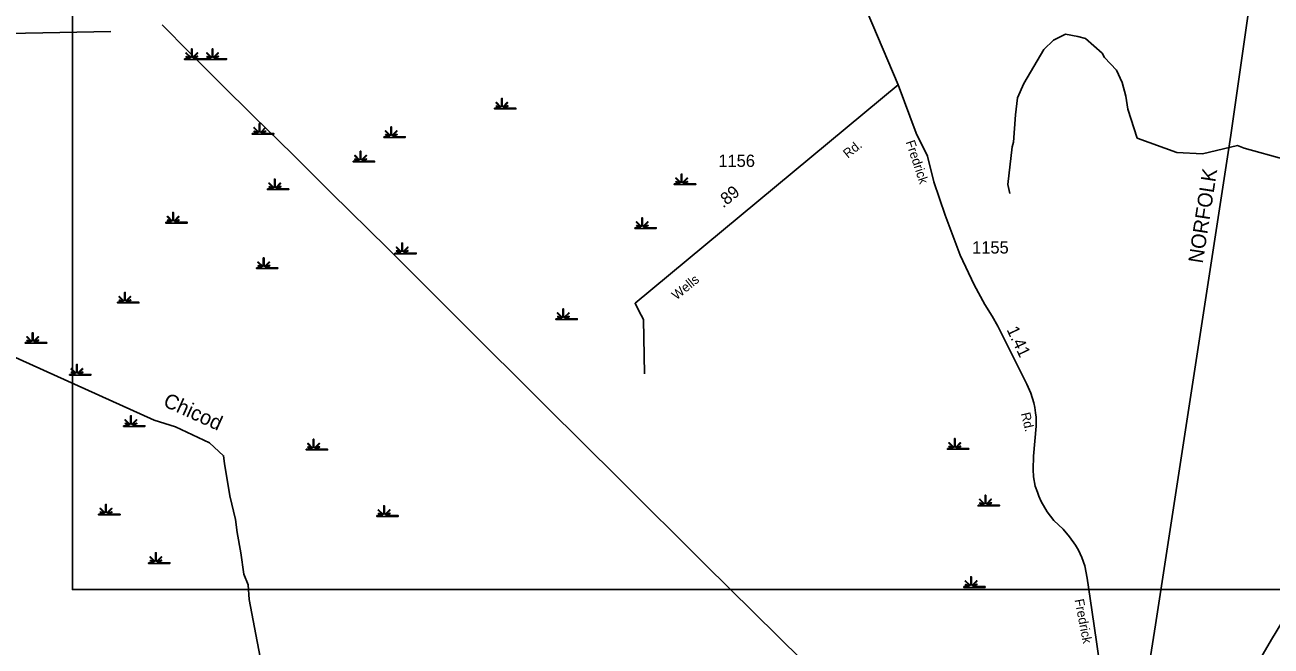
# Model space of a CAD drawing. Extents: x 2532689 to 2764727, y 536648 to 732970.
# Drawn here: x 2549089 to 2561755, y 635778 to 642091 of the extents above; entities that cross this region are included whole.
import ezdxf

# ---------------------------------------------------------------- set-up
doc = ezdxf.new("R2010")
doc.units = 0
for name, color, linetype in [('Exist Hydrographic Creek Single Shore', 7, 'Continuous'), ('Exist Hydrographic Creek Single Shore Label', 7, 'Continuous'), ('Exist Hydrographic Swamp CELL', 7, 'Continuous'), ('Exist Railroad Mainline', 7, 'Continuous'), ('Exist Railroad Mainline Label', 7, 'Continuous'), ('Exist Road Primary US Divided Attributed', 7, 'Continuous'), ('Exist Road Secondary Mileage Hundredths English Label', 7, 'Continuous'), ('Exist Road Secondary Type 20 Attributed', 7, 'Continuous'), ('Exist Road Secondary Type 51 Attributed', 7, 'Continuous'), ('Exist Road Secondary Type 51 Label', 7, 'Continuous'), ('Exist Road Secondary Type 51 Number Label', 7, 'Continuous'), ('Exist Utilities Electrical Transmission Line', 7, 'Continuous'), ('Map Preparation Inset Cut Line', 7, 'Continuous'), ('Map Preparation Longitude Latitude Lines', 7, 'Continuous')]:
    doc.layers.add(name, color=color, linetype=linetype)

msp = doc.modelspace()

# ---------------------------------------------------------------- linework, layer by layer
at = {"layer": 'Exist Hydrographic Creek Single Shore'}
for points in [[(2559098, 640377), (2559079, 640469), (2559122, 640851), (2559137, 640901), (2559157, 641178), (2559179, 641352), (2559242, 641496), (2559444, 641843), (2559542, 641935), (2559666, 641996), (2559791, 641975), (2559867, 641952), (2560037, 641804), (2560062, 641762), (2560182, 641633), (2560242, 641507), (2560278, 641367), (2560298, 641234), (2560395, 640942), (2560798, 640794), (2561056, 640782), (2561413, 640865), (2561481, 640838), (2561899, 640724)], [(2551589, 635080), (2551544, 635256), (2551534, 635380), (2551368, 636250), (2551357, 636400), (2551313, 636510), (2551284, 636726), (2551247, 636931), (2551228, 637065), (2551173, 637306), (2551118, 637632), (2551108, 637713), (2550964, 637845), (2550619, 638005), (2550401, 638075), (2548712, 638838)]]:
    msp.add_lwpolyline(points, dxfattribs=at)
at = {"layer": 'Exist Hydrographic Swamp CELL'}
for points in [[(2550710, 641748), (2550763, 641748), (2550765, 641751), (2550726, 641766), (2550729, 641772), (2550767, 641756), (2550769, 641759), (2550724, 641803), (2550729, 641808), (2550775, 641763), (2550781, 641765), (2550781, 641848), (2550788, 641848), (2550788, 641765), (2550795, 641763), (2550840, 641808), (2550845, 641803), (2550801, 641759), (2550803, 641755), (2550843, 641774), (2550846, 641769), (2550805, 641751), (2550807, 641748), (2550928, 641748), (2550928, 641741), (2550710, 641741)], [(2550921, 641748), (2550974, 641748), (2550976, 641751), (2550937, 641766), (2550940, 641772), (2550978, 641756), (2550980, 641759), (2550935, 641803), (2550940, 641808), (2550986, 641763), (2550992, 641765), (2550992, 641848), (2550999, 641848), (2550999, 641765), (2551006, 641763), (2551051, 641808), (2551056, 641803), (2551012, 641759), (2551014, 641755), (2551054, 641774), (2551057, 641769), (2551016, 641751), (2551018, 641748), (2551139, 641748), (2551139, 641741), (2550921, 641741)], [(2553862, 641245), (2553915, 641245), (2553917, 641248), (2553879, 641263), (2553881, 641268), (2553919, 641253), (2553921, 641256), (2553876, 641300), (2553881, 641305), (2553927, 641260), (2553933, 641262), (2553933, 641345), (2553940, 641345), (2553940, 641262), (2553947, 641260), (2553992, 641305), (2553997, 641300), (2553953, 641256), (2553955, 641252), (2553996, 641271), (2553998, 641265), (2553957, 641248), (2553959, 641245), (2554080, 641245), (2554080, 641238), (2553862, 641238)], [(2551400, 640988), (2551453, 640988), (2551455, 640992), (2551417, 641007), (2551420, 641012), (2551457, 640996), (2551459, 640999), (2551414, 641044), (2551420, 641049), (2551465, 641003), (2551471, 641006), (2551471, 641089), (2551478, 641089), (2551478, 641006), (2551485, 641003), (2551530, 641049), (2551535, 641044), (2551491, 640999), (2551493, 640996), (2551534, 641014), (2551536, 641009), (2551495, 640991), (2551497, 640988), (2551618, 640988), (2551618, 640981), (2551400, 640981)], [(2552737, 640955), (2552790, 640955), (2552792, 640959), (2552753, 640973), (2552756, 640979), (2552794, 640963), (2552796, 640966), (2552751, 641010), (2552756, 641015), (2552802, 640970), (2552808, 640972), (2552808, 641055), (2552815, 641055), (2552815, 640972), (2552822, 640970), (2552867, 641015), (2552872, 641010), (2552828, 640966), (2552830, 640962), (2552870, 640981), (2552873, 640976), (2552832, 640958), (2552834, 640955), (2552955, 640955), (2552955, 640948), (2552737, 640948)], [(2552426, 640706), (2552479, 640706), (2552481, 640710), (2552442, 640725), (2552445, 640730), (2552483, 640714), (2552485, 640717), (2552440, 640762), (2552445, 640767), (2552491, 640721), (2552497, 640724), (2552497, 640807), (2552504, 640807), (2552504, 640724), (2552510, 640721), (2552556, 640767), (2552561, 640762), (2552516, 640717), (2552518, 640714), (2552559, 640732), (2552562, 640727), (2552521, 640709), (2552522, 640706), (2552643, 640706), (2552643, 640699), (2552426, 640699)], [(2551554, 640425), (2551607, 640425), (2551609, 640429), (2551570, 640443), (2551573, 640449), (2551611, 640433), (2551613, 640436), (2551568, 640480), (2551573, 640485), (2551619, 640440), (2551625, 640442), (2551625, 640525), (2551632, 640525), (2551632, 640442), (2551638, 640440), (2551684, 640485), (2551689, 640480), (2551644, 640436), (2551646, 640432), (2551687, 640451), (2551690, 640446), (2551649, 640428), (2551650, 640425), (2551771, 640425), (2551771, 640418), (2551554, 640418)], [(2555689, 640476), (2555742, 640476), (2555744, 640479), (2555705, 640494), (2555708, 640499), (2555746, 640484), (2555748, 640486), (2555703, 640531), (2555708, 640536), (2555754, 640491), (2555760, 640493), (2555760, 640576), (2555767, 640576), (2555767, 640493), (2555774, 640491), (2555819, 640536), (2555824, 640531), (2555780, 640486), (2555782, 640483), (2555822, 640501), (2555825, 640496), (2555784, 640479), (2555786, 640476), (2555907, 640476), (2555907, 640468), (2555689, 640468)], [(2550520, 640085), (2550573, 640086), (2550575, 640089), (2550537, 640104), (2550540, 640109), (2550577, 640093), (2550579, 640096), (2550534, 640141), (2550540, 640146), (2550585, 640100), (2550591, 640103), (2550591, 640186), (2550598, 640186), (2550598, 640103), (2550605, 640100), (2550650, 640146), (2550655, 640141), (2550611, 640096), (2550613, 640093), (2550654, 640111), (2550656, 640106), (2550615, 640088), (2550617, 640086), (2550738, 640085), (2550738, 640078), (2550520, 640078)], [(2555288, 640030), (2555341, 640030), (2555343, 640033), (2555304, 640048), (2555307, 640053), (2555345, 640038), (2555347, 640041), (2555302, 640085), (2555307, 640090), (2555353, 640045), (2555359, 640047), (2555359, 640130), (2555366, 640130), (2555366, 640047), (2555372, 640045), (2555418, 640090), (2555423, 640085), (2555379, 640041), (2555381, 640037), (2555421, 640056), (2555424, 640051), (2555383, 640033), (2555384, 640030), (2555506, 640030), (2555506, 640023), (2555288, 640023)], [(2552848, 639773), (2552901, 639773), (2552903, 639777), (2552865, 639792), (2552868, 639797), (2552905, 639781), (2552907, 639784), (2552863, 639829), (2552868, 639834), (2552913, 639788), (2552919, 639791), (2552919, 639874), (2552927, 639874), (2552927, 639791), (2552933, 639788), (2552978, 639834), (2552983, 639829), (2552939, 639784), (2552941, 639781), (2552982, 639799), (2552984, 639794), (2552943, 639776), (2552945, 639773), (2553066, 639773), (2553066, 639766), (2552848, 639766)], [(2551441, 639623), (2551494, 639623), (2551496, 639626), (2551458, 639641), (2551461, 639646), (2551498, 639631), (2551500, 639634), (2551456, 639678), (2551461, 639683), (2551506, 639638), (2551512, 639640), (2551512, 639723), (2551520, 639723), (2551520, 639640), (2551526, 639638), (2551571, 639683), (2551576, 639678), (2551532, 639634), (2551534, 639630), (2551575, 639649), (2551577, 639644), (2551536, 639626), (2551538, 639623), (2551659, 639623), (2551659, 639616), (2551441, 639616)], [(2550030, 639272), (2550083, 639272), (2550085, 639275), (2550046, 639290), (2550049, 639295), (2550087, 639280), (2550089, 639283), (2550044, 639327), (2550049, 639332), (2550095, 639287), (2550101, 639289), (2550101, 639372), (2550108, 639372), (2550108, 639289), (2550115, 639287), (2550160, 639332), (2550165, 639327), (2550121, 639283), (2550123, 639279), (2550163, 639298), (2550166, 639293), (2550125, 639275), (2550127, 639272), (2550248, 639272), (2550248, 639265), (2550030, 639265)], [(2554486, 639105), (2554539, 639105), (2554541, 639108), (2554502, 639123), (2554505, 639128), (2554543, 639112), (2554545, 639115), (2554500, 639160), (2554505, 639165), (2554551, 639120), (2554557, 639122), (2554557, 639205), (2554564, 639205), (2554564, 639122), (2554570, 639120), (2554616, 639165), (2554621, 639160), (2554576, 639115), (2554578, 639112), (2554619, 639130), (2554622, 639125), (2554581, 639108), (2554582, 639105), (2554703, 639105), (2554703, 639097), (2554486, 639097)], [(2549093, 638863), (2549145, 638863), (2549147, 638866), (2549109, 638881), (2549112, 638886), (2549150, 638871), (2549151, 638874), (2549107, 638918), (2549112, 638923), (2549157, 638878), (2549164, 638880), (2549164, 638963), (2549171, 638963), (2549171, 638880), (2549177, 638878), (2549222, 638923), (2549228, 638918), (2549183, 638874), (2549185, 638870), (2549226, 638889), (2549228, 638884), (2549187, 638866), (2549189, 638863), (2549310, 638863), (2549310, 638856), (2549093, 638856)], [(2549543, 638539), (2549595, 638539), (2549597, 638543), (2549559, 638558), (2549562, 638563), (2549600, 638547), (2549601, 638550), (2549557, 638594), (2549562, 638600), (2549607, 638554), (2549614, 638556), (2549614, 638640), (2549621, 638640), (2549621, 638556), (2549627, 638554), (2549672, 638600), (2549678, 638594), (2549633, 638550), (2549635, 638546), (2549676, 638565), (2549679, 638560), (2549638, 638542), (2549639, 638539), (2549760, 638539), (2549760, 638532), (2549543, 638532)], [(2550091, 638018), (2550144, 638018), (2550146, 638022), (2550108, 638037), (2550111, 638042), (2550148, 638026), (2550150, 638029), (2550105, 638074), (2550111, 638079), (2550156, 638033), (2550162, 638036), (2550162, 638119), (2550169, 638119), (2550169, 638036), (2550176, 638033), (2550221, 638079), (2550226, 638074), (2550182, 638029), (2550184, 638026), (2550225, 638044), (2550227, 638039), (2550186, 638021), (2550188, 638018), (2550309, 638018), (2550309, 638011), (2550091, 638011)], [(2551948, 637779), (2552000, 637779), (2552002, 637783), (2551964, 637798), (2551967, 637803), (2552005, 637787), (2552006, 637790), (2551962, 637834), (2551967, 637840), (2552012, 637794), (2552019, 637797), (2552019, 637880), (2552026, 637880), (2552026, 637797), (2552032, 637794), (2552078, 637840), (2552083, 637834), (2552038, 637790), (2552040, 637786), (2552081, 637805), (2552084, 637800), (2552043, 637782), (2552044, 637779), (2552165, 637779), (2552165, 637772), (2551948, 637772)], [(2558465, 637785), (2558518, 637785), (2558520, 637789), (2558481, 637804), (2558484, 637809), (2558522, 637793), (2558524, 637796), (2558479, 637841), (2558484, 637846), (2558530, 637800), (2558536, 637803), (2558536, 637886), (2558543, 637886), (2558543, 637803), (2558549, 637800), (2558595, 637846), (2558600, 637841), (2558555, 637796), (2558557, 637793), (2558598, 637811), (2558601, 637806), (2558560, 637788), (2558561, 637785), (2558682, 637785), (2558682, 637778), (2558465, 637778)], [(2549838, 637118), (2549891, 637118), (2549893, 637121), (2549854, 637136), (2549857, 637141), (2549895, 637126), (2549897, 637128), (2549852, 637173), (2549857, 637178), (2549903, 637133), (2549909, 637135), (2549909, 637218), (2549916, 637218), (2549916, 637135), (2549923, 637133), (2549968, 637178), (2549973, 637173), (2549929, 637128), (2549931, 637125), (2549971, 637143), (2549974, 637138), (2549933, 637121), (2549935, 637118), (2550056, 637118), (2550056, 637111), (2549838, 637111)], [(2558777, 637210), (2558829, 637210), (2558831, 637214), (2558793, 637229), (2558796, 637234), (2558834, 637218), (2558835, 637221), (2558791, 637266), (2558796, 637271), (2558841, 637225), (2558848, 637228), (2558848, 637311), (2558855, 637311), (2558855, 637228), (2558861, 637225), (2558907, 637271), (2558912, 637266), (2558867, 637221), (2558869, 637217), (2558910, 637236), (2558913, 637231), (2558872, 637213), (2558873, 637210), (2558994, 637210), (2558994, 637203), (2558777, 637203)], [(2552665, 637104), (2552718, 637104), (2552720, 637107), (2552681, 637122), (2552684, 637127), (2552722, 637112), (2552724, 637114), (2552679, 637159), (2552684, 637164), (2552730, 637119), (2552736, 637121), (2552736, 637204), (2552743, 637204), (2552743, 637121), (2552750, 637119), (2552795, 637164), (2552800, 637159), (2552756, 637114), (2552758, 637111), (2552798, 637129), (2552801, 637124), (2552760, 637107), (2552762, 637104), (2552883, 637104), (2552883, 637096), (2552665, 637096)], [(2550344, 636625), (2550397, 636625), (2550399, 636629), (2550361, 636644), (2550364, 636649), (2550401, 636633), (2550403, 636636), (2550359, 636680), (2550364, 636686), (2550409, 636640), (2550415, 636642), (2550415, 636726), (2550423, 636726), (2550423, 636642), (2550429, 636640), (2550474, 636686), (2550479, 636680), (2550435, 636636), (2550437, 636632), (2550478, 636651), (2550480, 636646), (2550439, 636628), (2550441, 636625), (2550562, 636625), (2550562, 636618), (2550344, 636618)], [(2558631, 636382), (2558683, 636382), (2558685, 636385), (2558647, 636400), (2558650, 636405), (2558688, 636390), (2558689, 636392), (2558645, 636437), (2558650, 636442), (2558695, 636397), (2558702, 636399), (2558702, 636482), (2558709, 636482), (2558709, 636399), (2558715, 636397), (2558760, 636442), (2558766, 636437), (2558721, 636392), (2558723, 636389), (2558764, 636407), (2558766, 636402), (2558725, 636385), (2558727, 636382), (2558848, 636382), (2558848, 636374), (2558631, 636374)]]:
    msp.add_lwpolyline(points, close=True, dxfattribs=at)
at = {"layer": 'Exist Railroad Mainline'}
msp.add_lwpolyline([(2559836, 631017), (2560198, 633565), (2560580, 635992), (2561345, 640971), (2561535, 642299), (2561640, 643031)], dxfattribs=at)
at = {"layer": 'Exist Road Primary US Divided Attributed'}
msp.add_lwpolyline([(2560987, 634551), (2561007, 634587), (2561581, 635545), (2561649, 635658), (2561760, 635844), (2561864, 636016), (2561980, 636211), (2562085, 636388), (2562163, 636518), (2562307, 636758), (2562445, 636986), (2562519, 637112), (2562643, 637320), (2562996, 637912), (2563069, 638047), (2563124, 638171), (2563159, 638272), (2563197, 638390)], dxfattribs=at)
at = {"layer": 'Exist Road Secondary Type 20 Attributed'}
msp.add_lwpolyline([(2557966, 641483), (2555291, 639262), (2555330, 639185), (2555377, 639096), (2555385, 638545)], dxfattribs=at)
at = {"layer": 'Exist Road Secondary Type 51 Attributed'}
for points in [[(2557966, 641483), (2557648, 642225), (2557577, 642400), (2557487, 642620), (2557407, 642842), (2557384, 642904), (2557366, 642976), (2557344, 643077), (2557318, 643209), (2557279, 643460), (2557236, 643759), (2557193, 644009), (2557175, 644120), (2557162, 644212)], [(2560043, 635375), (2559983, 635798), (2559933, 636147), (2559887, 636469), (2559860, 636595), (2559831, 636679), (2559798, 636753), (2559767, 636803), (2559707, 636887), (2559640, 636965), (2559545, 637055), (2559478, 637142), (2559419, 637248), (2559393, 637300), (2559379, 637341), (2559357, 637403), (2559341, 637498), (2559336, 637574), (2559341, 637708), (2559368, 638013), (2559366, 638103), (2559360, 638150), (2559355, 638202), (2559342, 638250), (2559314, 638348), (2559273, 638441), (2558979, 639029), (2558921, 639132), (2558844, 639248), (2558736, 639450), (2558593, 639751), (2558442, 640159), (2558328, 640496), (2558261, 640758), (2558147, 640991), (2557966, 641483)]]:
    msp.add_lwpolyline(points, dxfattribs=at)
at = {"layer": 'Exist Utilities Electrical Transmission Line'}
msp.add_lwpolyline([(2550485, 642091), (2550758, 641816), (2551078, 641496), (2551416, 641162), (2551807, 640779), (2552200, 640385), (2552773, 639823), (2553500, 639096), (2554388, 638212), (2555128, 637476), (2556001, 636610), (2556993, 635630), (2557971, 634656), (2558273, 634360)], dxfattribs=at)
at = {"layer": 'Map Preparation Inset Cut Line'}
msp.add_lwpolyline([(2549571, 680600), (2610045, 680600), (2610045, 636352), (2549571, 636352)], close=True, dxfattribs=at)
at = {"layer": 'Map Preparation Longitude Latitude Lines'}
msp.add_lwpolyline([(2536991, 641785), (2545629, 641941), (2549962, 642023)], dxfattribs=at)

# ---------------------------------------------------------------- texts
at = {"layer": 'Exist Hydrographic Creek Single Shore Label'}
msp.add_text('Chicod', height=150, rotation=335.7095, dxfattribs=at).set_placement((2550484, 638221))
at = {"layer": 'Exist Railroad Mainline Label'}
msp.add_text('NORFOLK', height=150, rotation=81.2085, dxfattribs=at).set_placement((2561060, 639662))
at = {"layer": 'Exist Road Secondary Mileage Hundredths English Label'}
for s, rotation, p in [('.89', 39.6992, (2556186, 640225)), ('1.41', 295.4323, (2559064, 638994))]:
    msp.add_text(s, height=125, rotation=rotation, dxfattribs=at).set_placement(p)
at = {"layer": 'Exist Road Secondary Type 51 Label'}
for s, rotation, p in [('Rd.', 39.3079, (2557453, 640731)), ('Fredrick', 288.369, (2558040, 640902)), ('Wells', 39.3079, (2555711, 639291)), ('Rd.', 283.29, (2559212, 638142)), ('Fredrick', 280.8506, (2559757, 636248))]:
    msp.add_text(s, height=95, rotation=rotation, dxfattribs=at).set_placement(p)
at = {"layer": 'Exist Road Secondary Type 51 Number Label'}
msp.add_text('1156', height=125, dxfattribs=at).set_placement((2556137, 640648))
msp.add_text('1155', height=125, rotation=359.94, dxfattribs=at).set_placement((2558716, 639768))

doc.saveas('drawing.dxf')
